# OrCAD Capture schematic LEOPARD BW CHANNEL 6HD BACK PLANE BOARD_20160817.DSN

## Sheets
1 001 COVER PAGE: title: 001 COVER PAGE; rev: SA; company: Wiwynn Corporation; note: LEOPARD BW CHANNEL BACK PLANE BOARD; note: 8F, No.90, Xintai 5th Rd., Xizhi Dist,; note: New Taipei, Taiwan
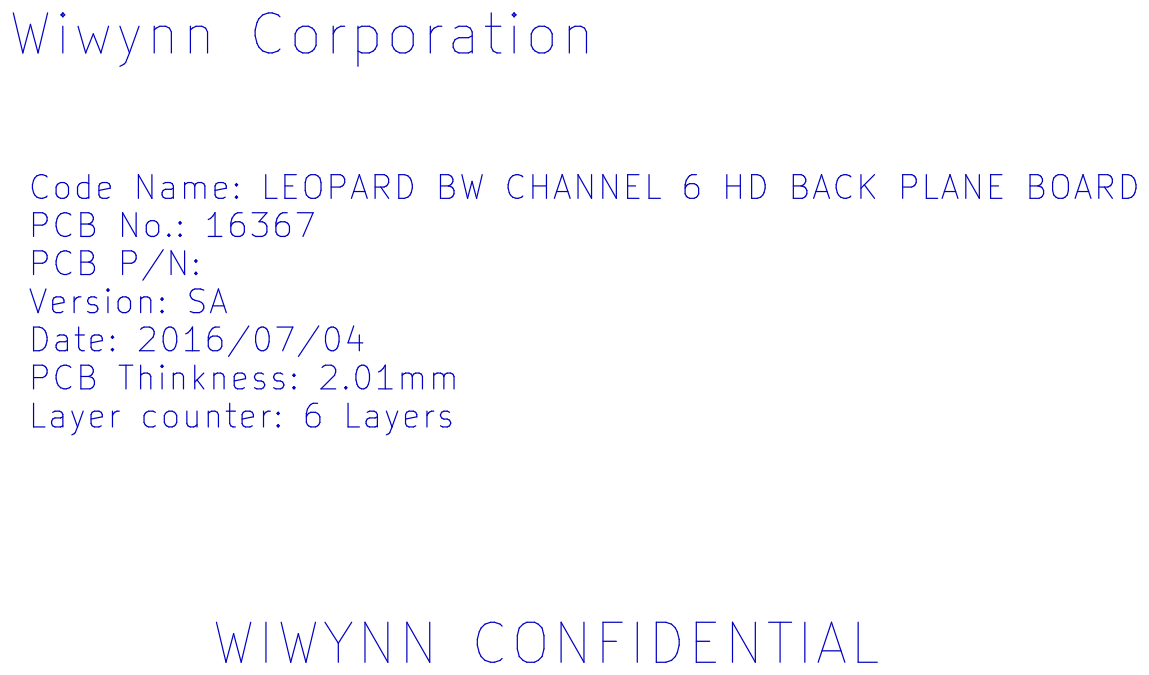
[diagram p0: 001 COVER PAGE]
2 007 SCREWS: size A4; title: 007 Screws; company: Wiwynn; note: 8F, 90, Sec.1, Hsin Tai Wu Rd.,; note: Hsichih, Taipei Hsien 221, Taiwan, R.O.C.
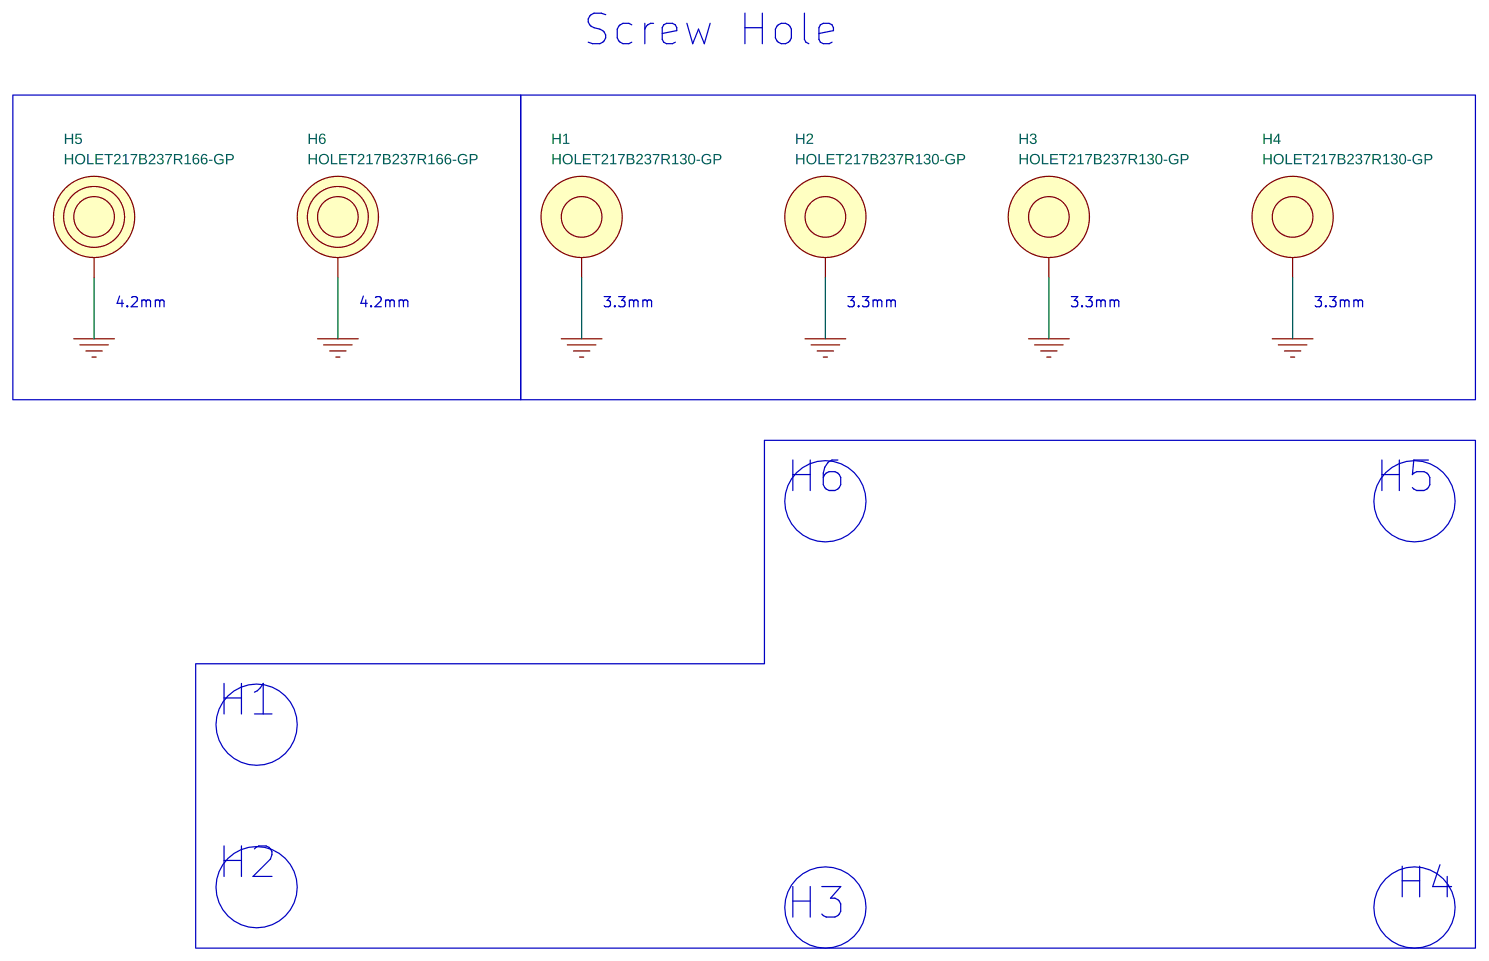
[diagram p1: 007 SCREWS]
3 006 MINISAS 1-2: size A3; title: 006 MiniSAS4i 1-2; company: Wiwynn; note: 8F, 90, Sec.1, Hsin Tai Wu Rd.,; note: Hsichih, Taipei Hsien 221, Taiwan, R.O.C.
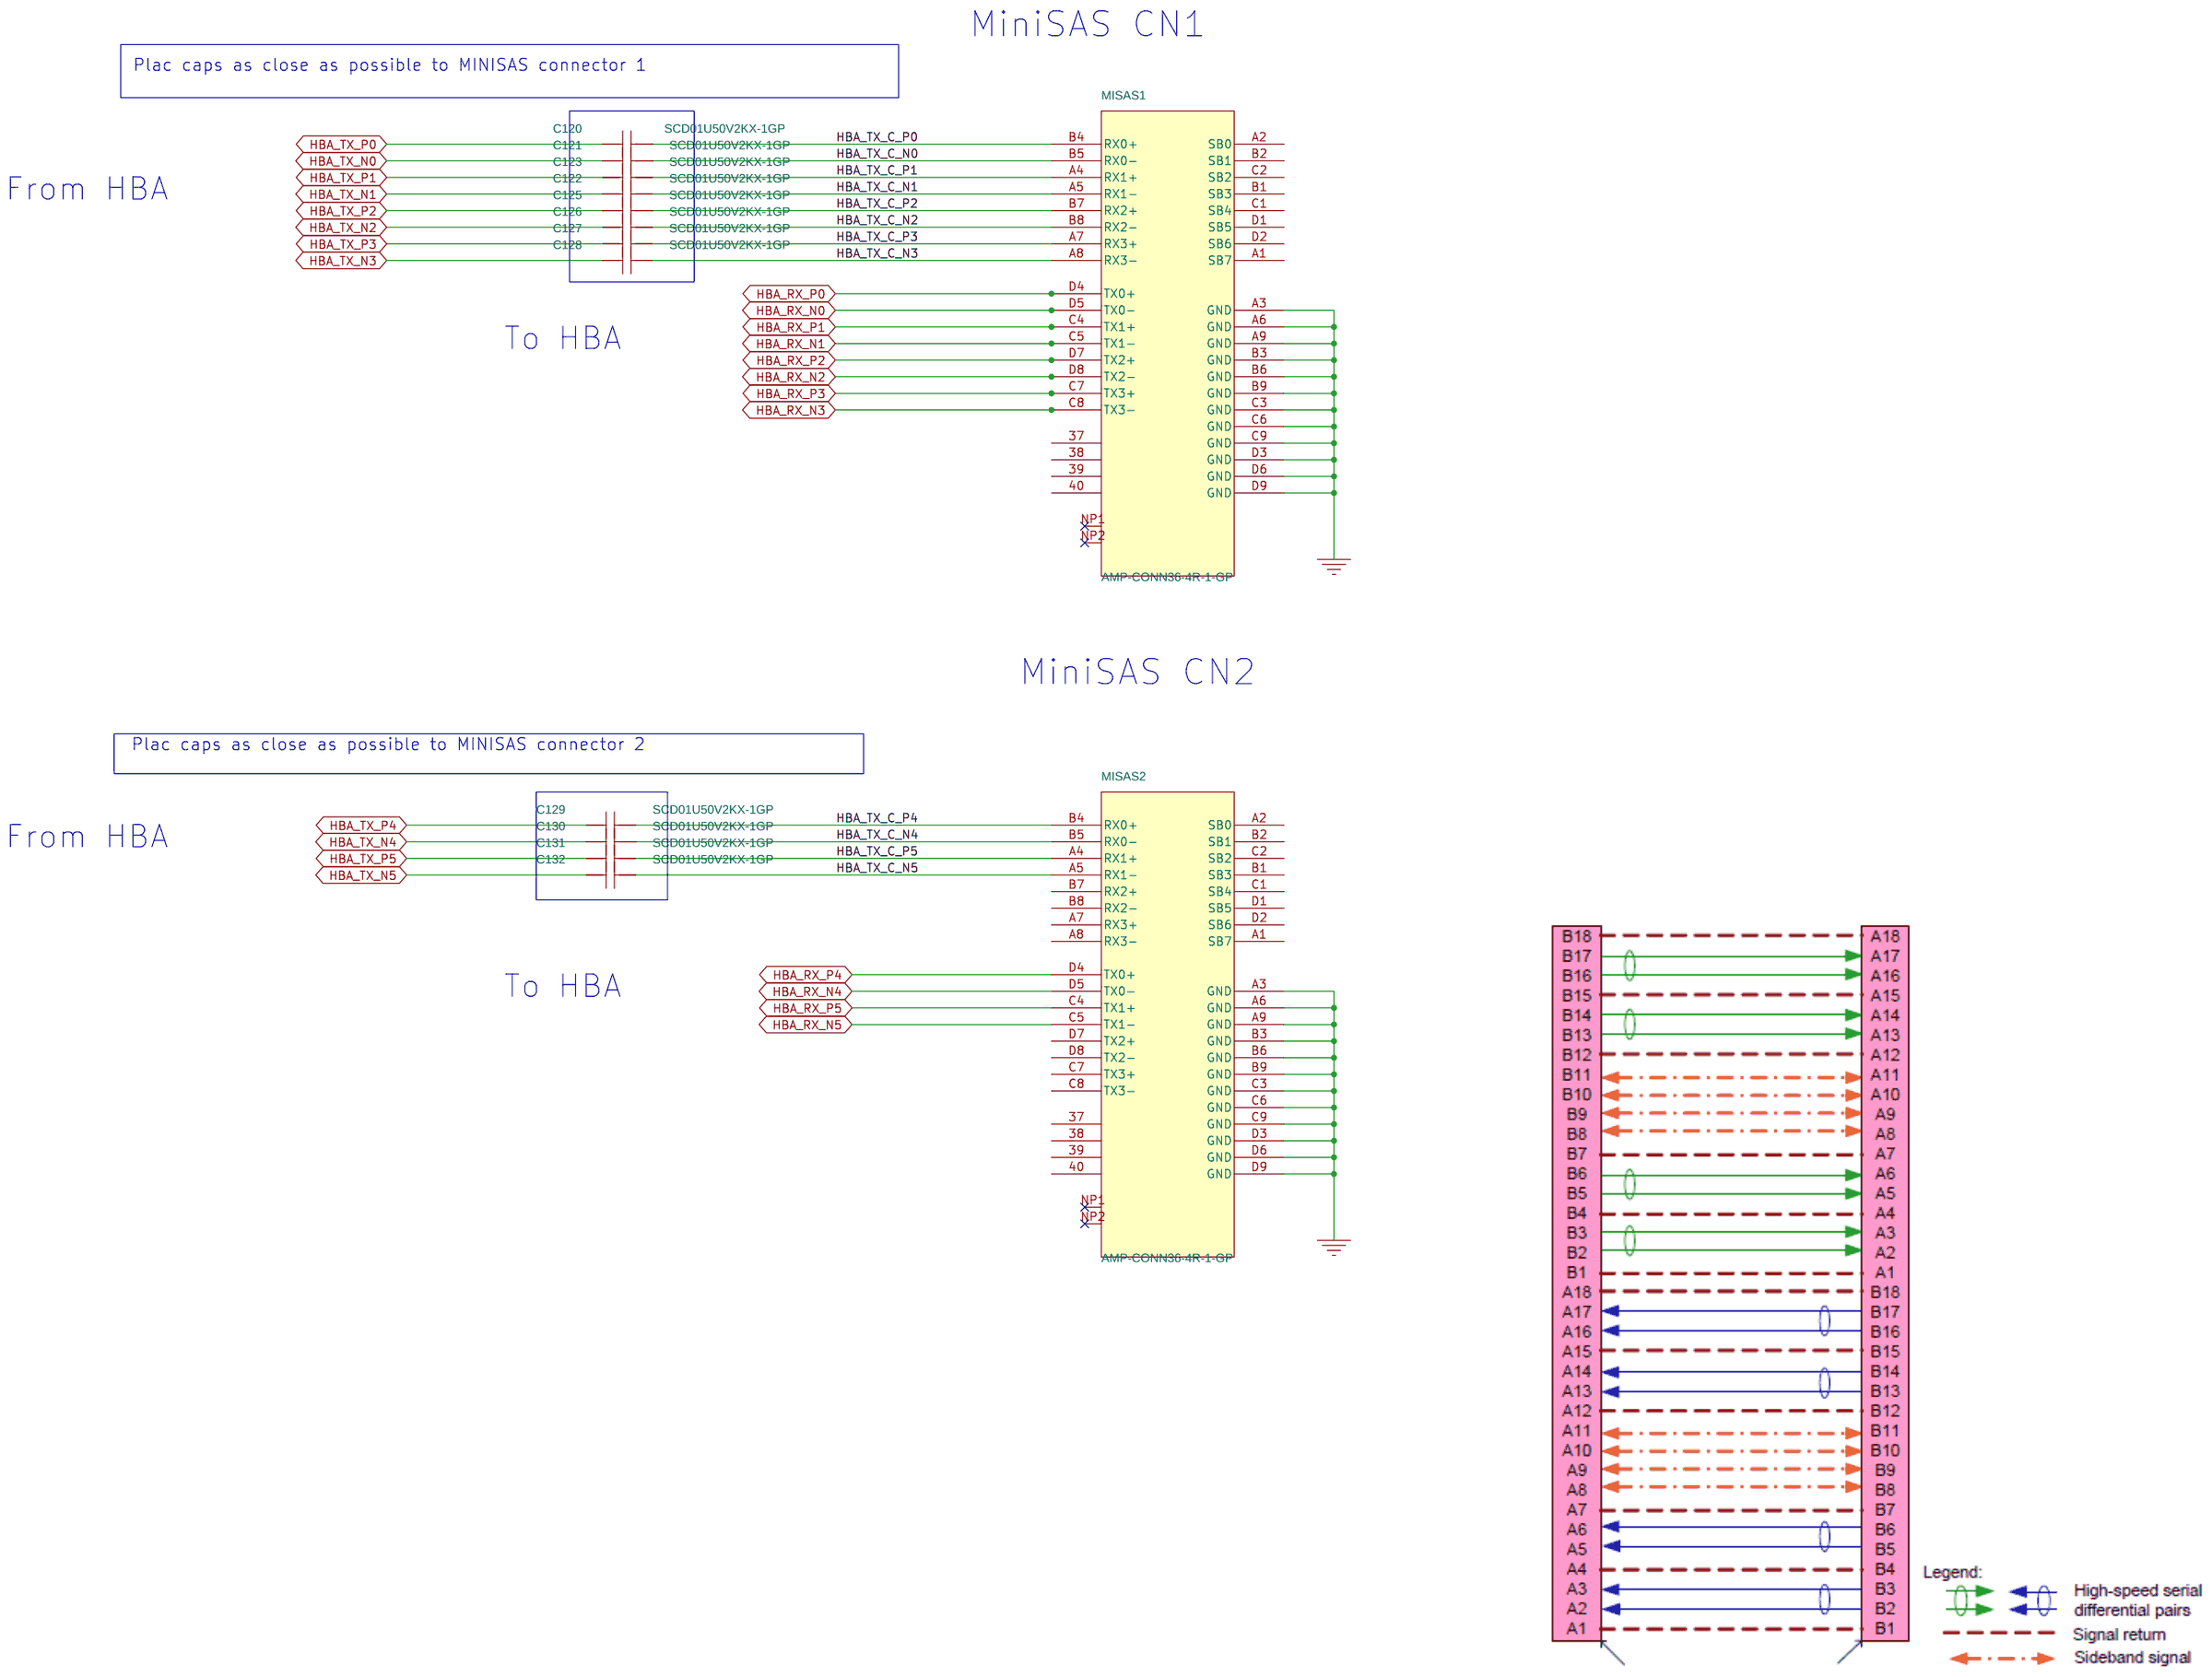
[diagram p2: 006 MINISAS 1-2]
4 005 POWER CONNECTOR: size A3; title: 005 PWR CN; company: Wiwynn; note: 8F, 90, Sec.1, Hsin Tai Wu Rd.,; note: Hsichih, Taipei Hsien 221, Taiwan, R.O.C.
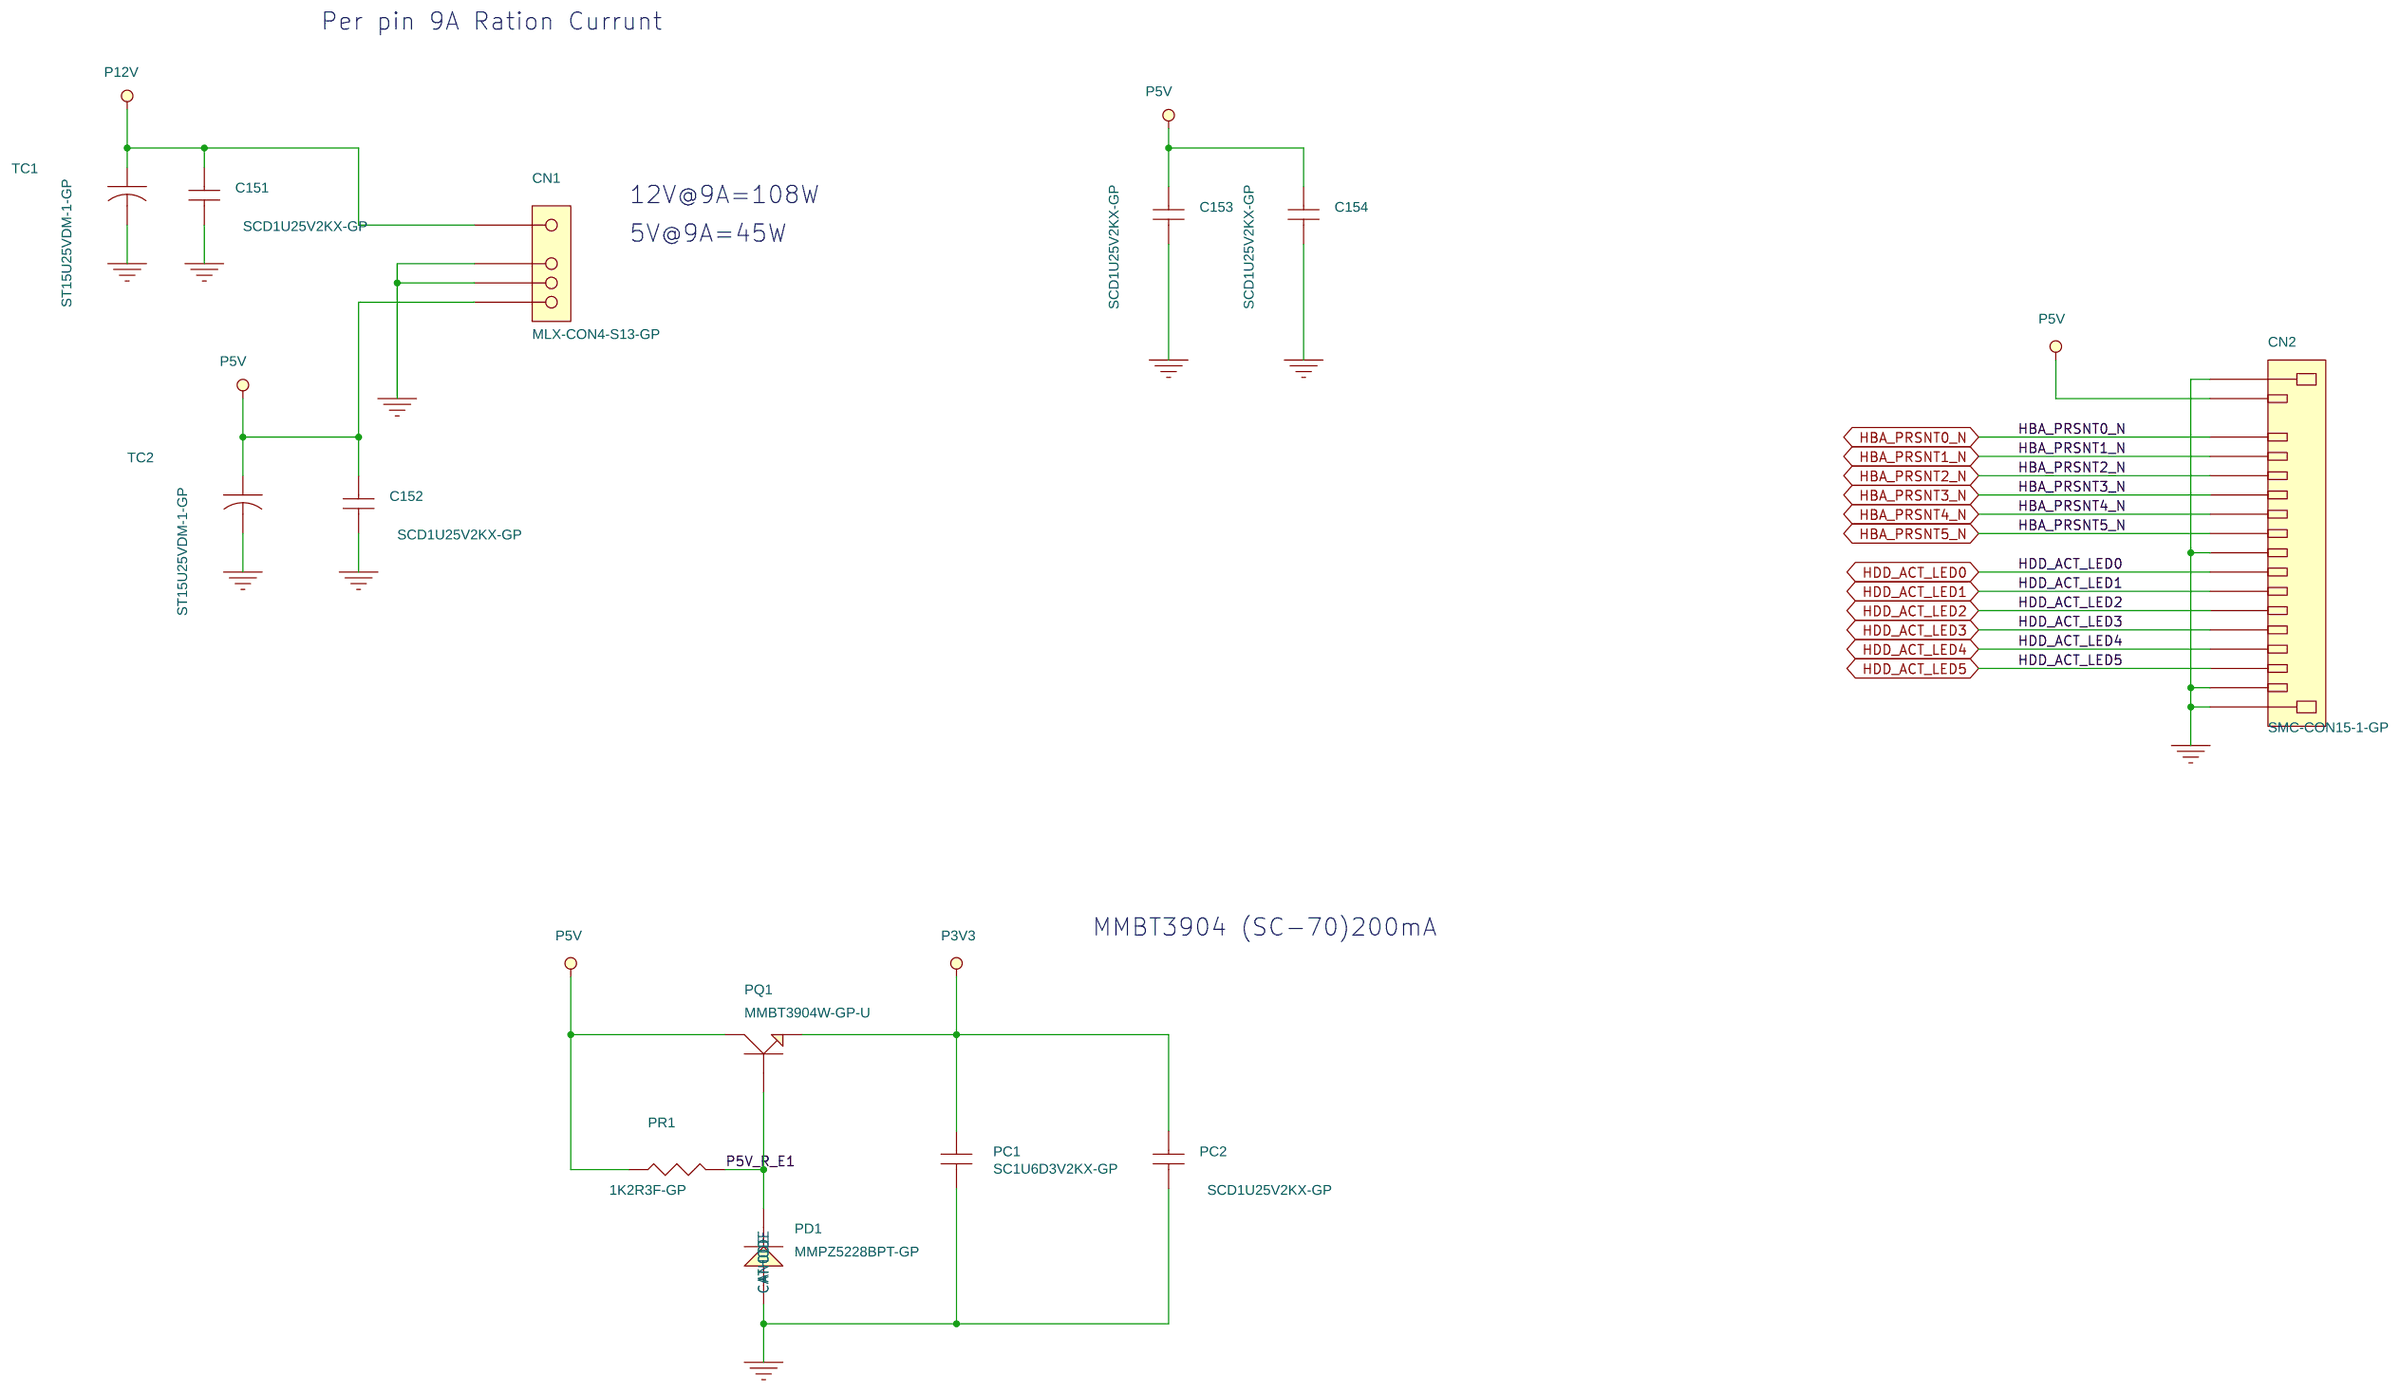
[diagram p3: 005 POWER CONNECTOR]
5 004 HDD SATA 5-6: size A2; title: 004 HDD SATA 5-6; company: Wiwynn; note: 8F, 90, Sec.1, Hsin Tai Wu Rd.,; note: Hsichih, Taipei Hsien 221, Taiwan, R.O.C.
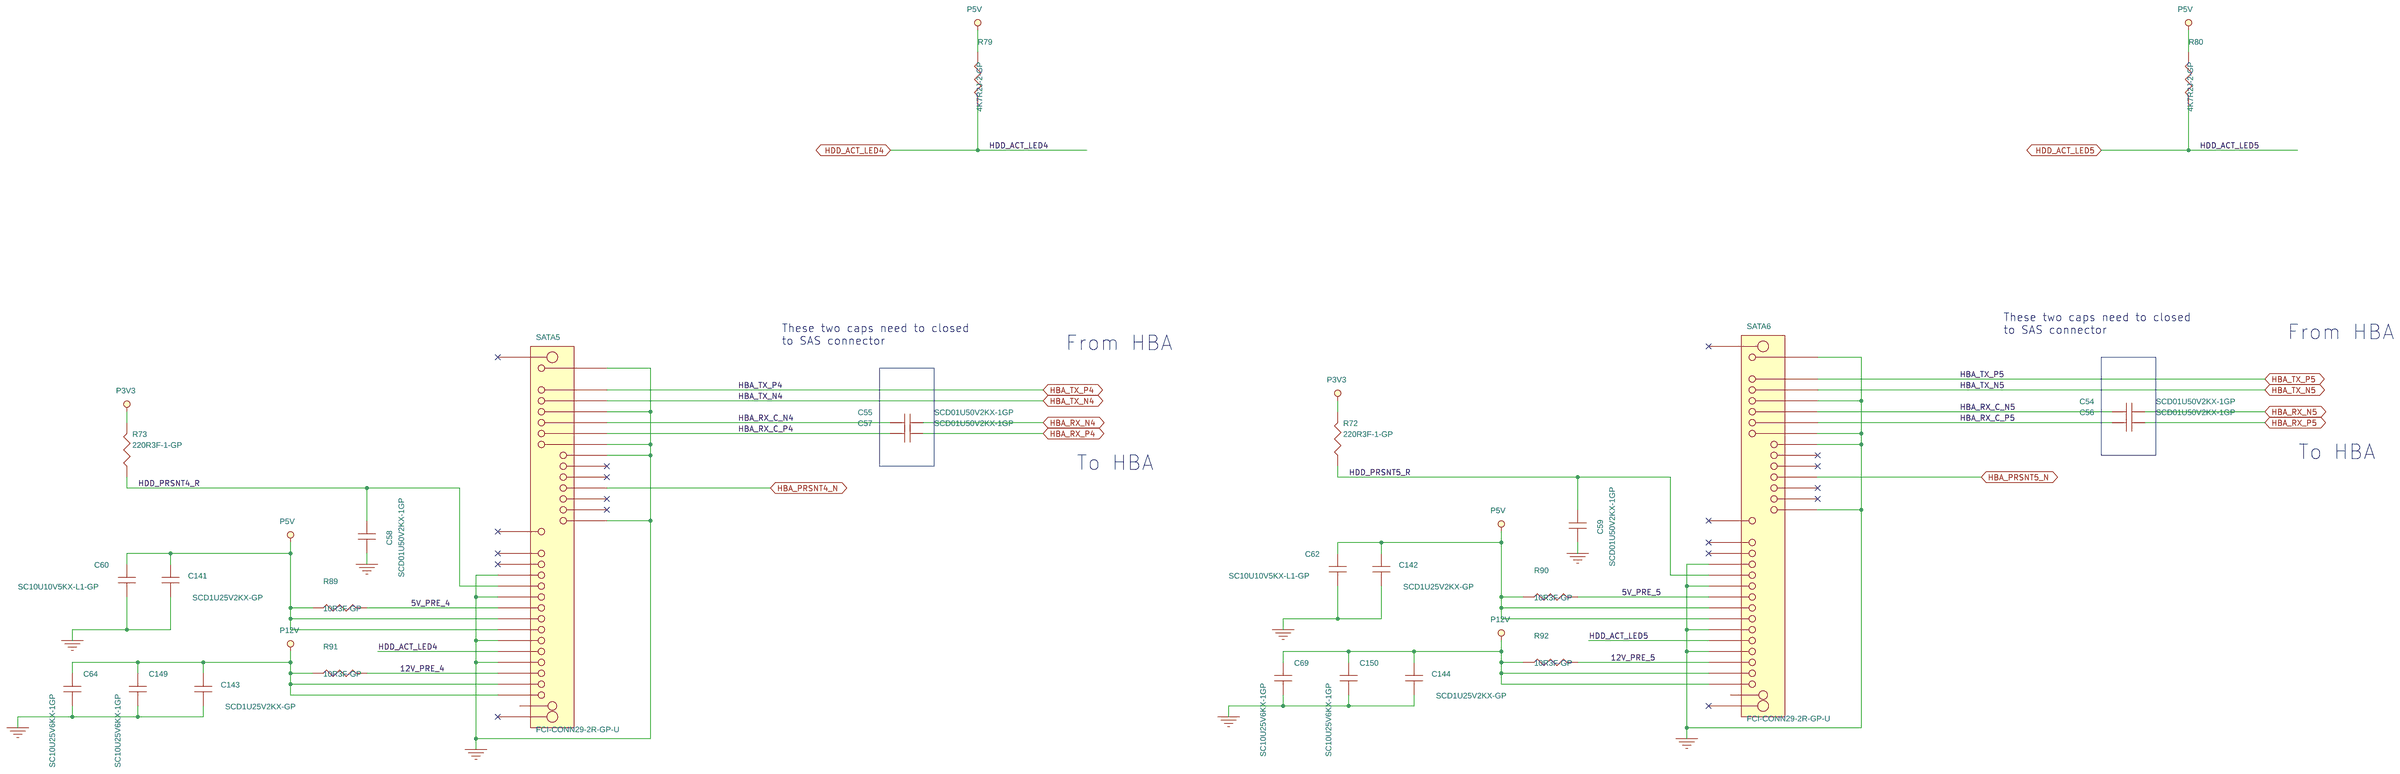
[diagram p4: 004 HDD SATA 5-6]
6 003 HDD SATA 1-4: size A2; title: 003 HDD SATA 1-4; company: Wiwynn; note: 8F, 90, Sec.1, Hsin Tai Wu Rd.,; note: Hsichih, Taipei Hsien 221, Taiwan, R.O.C.
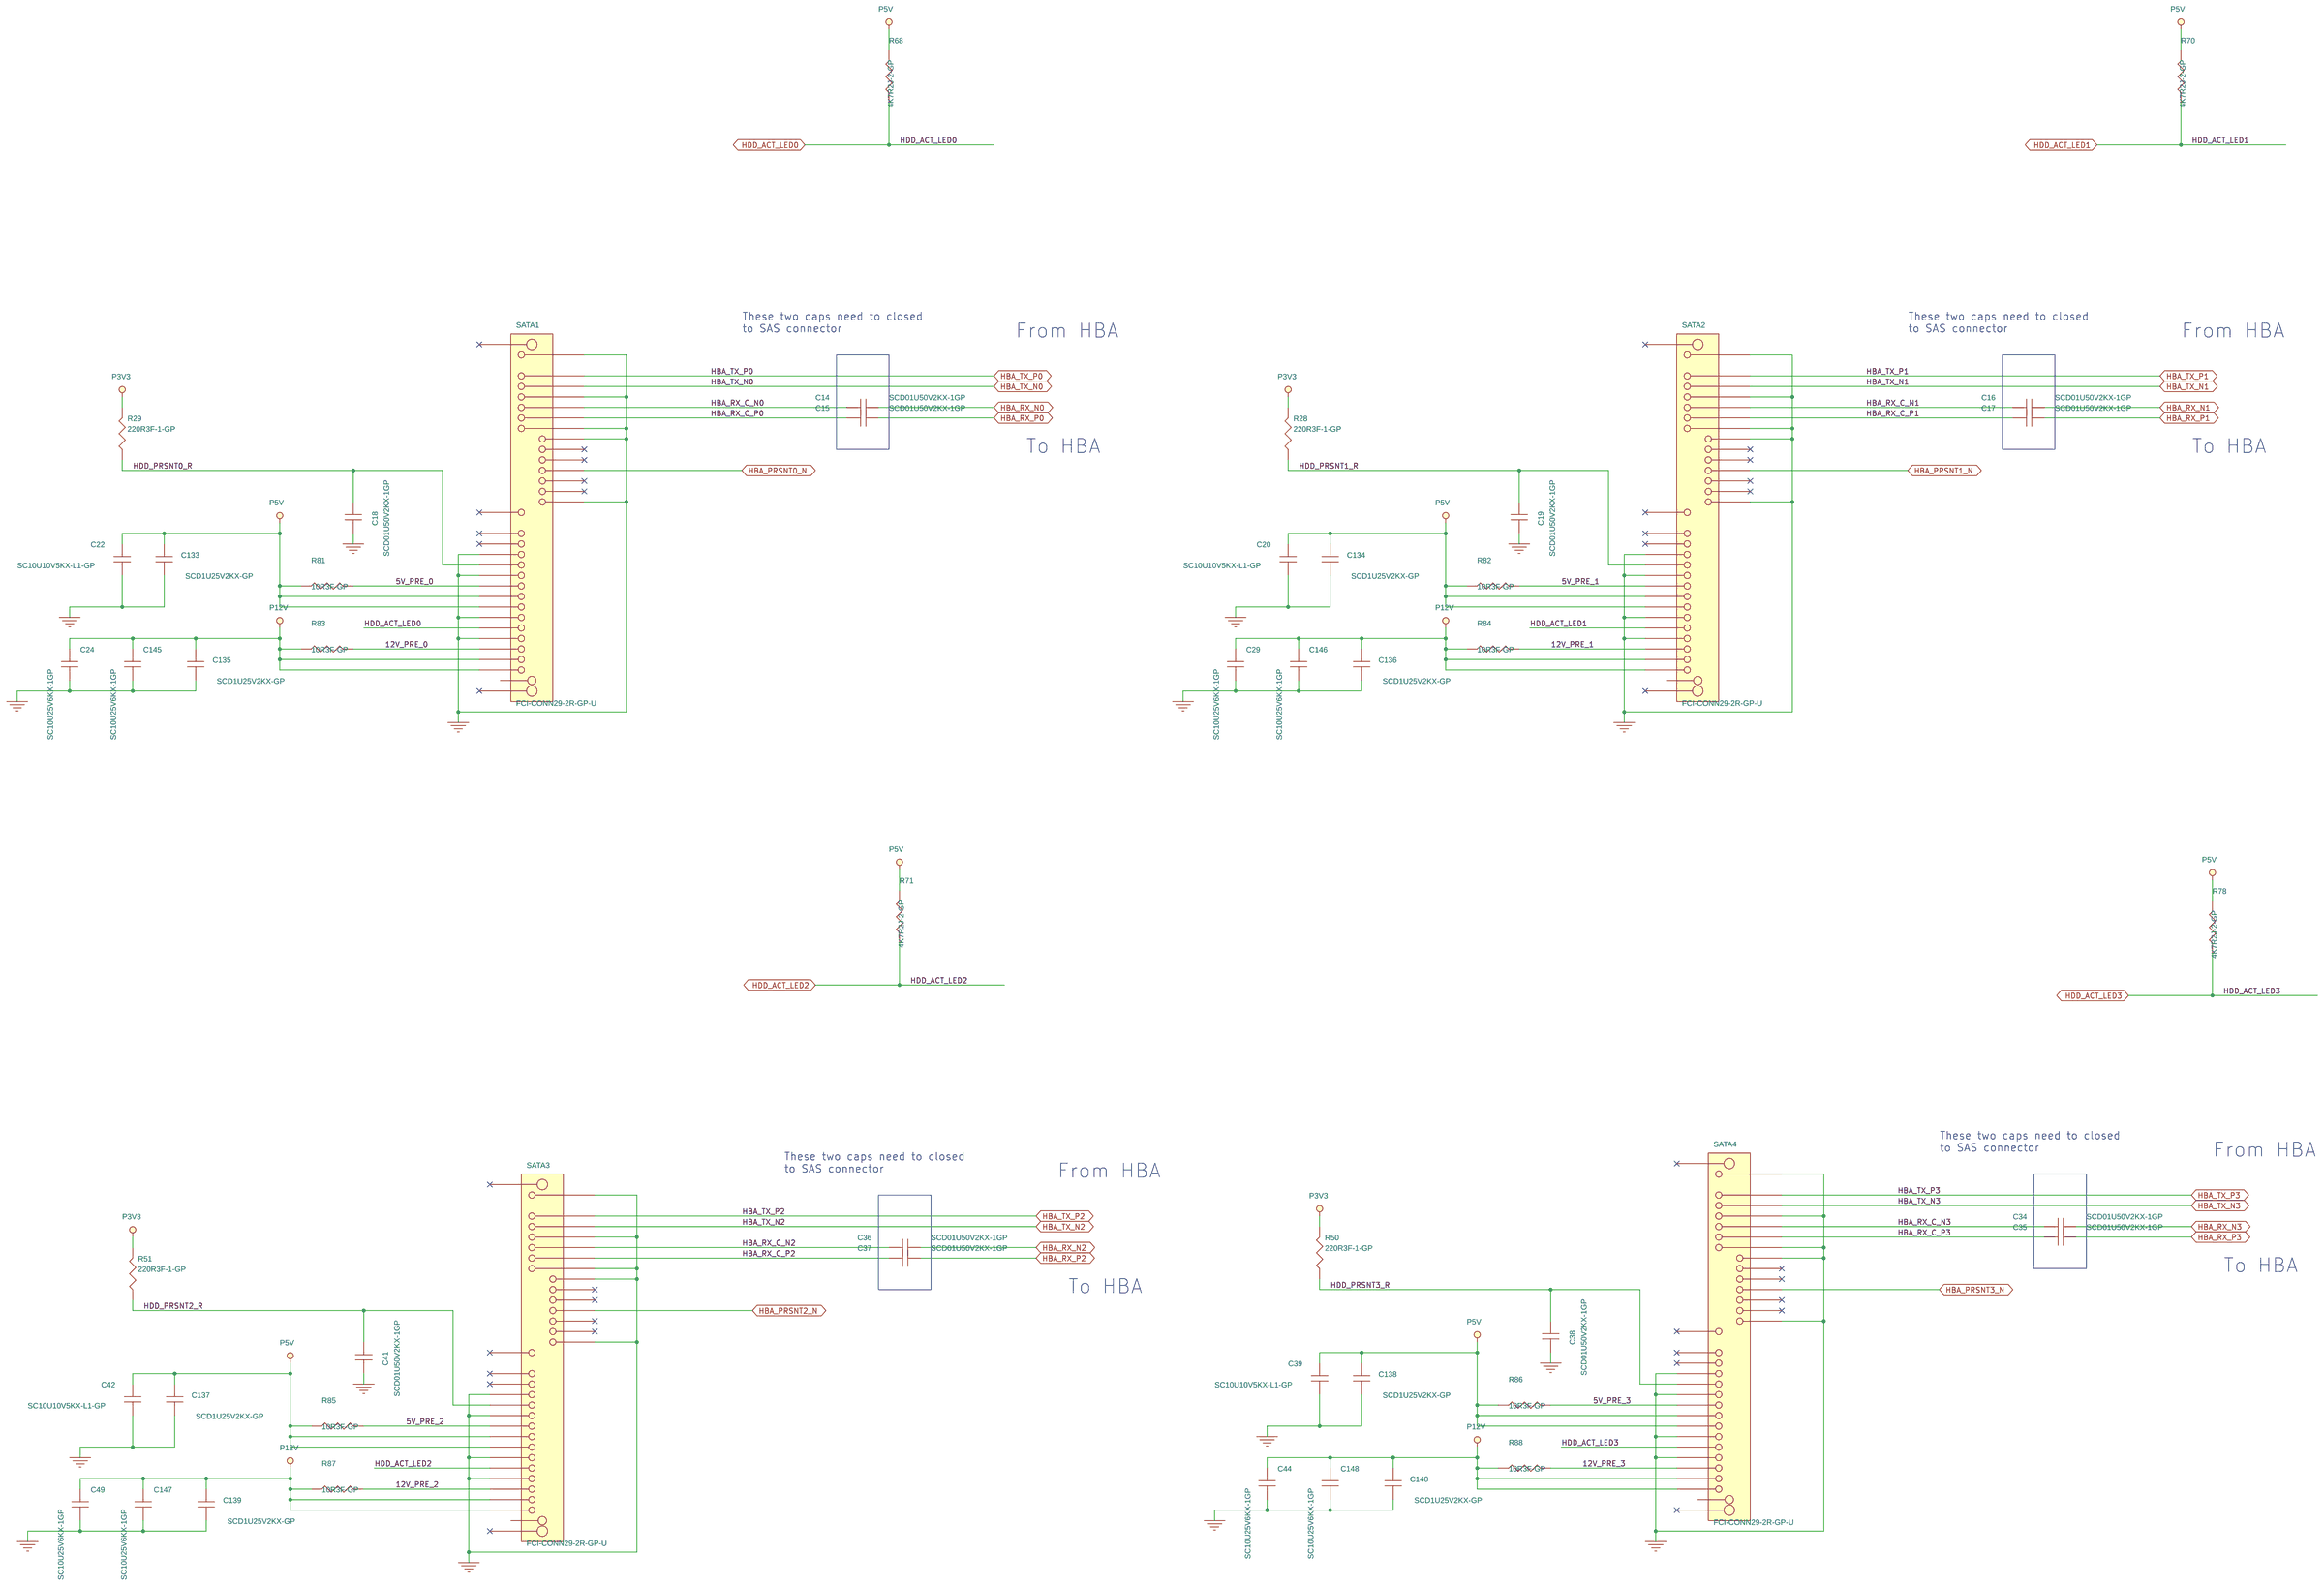
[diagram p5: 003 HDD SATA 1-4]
7 002 BLOCK DIAGRAM: title: 002 BLOCK DIAGRAM; company: Wiwynn; note: 8F, 90, Sec.1, Hsin Tai Wu Rd.,; note: Hsichih, Taipei Hsien 221, Taiwan, R.O.C.

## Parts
sheet 003 HDD SATA 1-4
C14  SCD01U50V2KX-1GP  [C402H22]
C15  SCD01U50V2KX-1GP  [C402H22]
C16  SCD01U50V2KX-1GP  [C402H22]
C17  SCD01U50V2KX-1GP  [C402H22]
C18  SCD01U50V2KX-1GP  [C402H22]
C19  SCD01U50V2KX-1GP  [C402H22]
C20  SC10U10V5KX-L1-GP  [C805H58]
C22  SC10U10V5KX-L1-GP  [C805H58]
C24  SC10U25V6KX-1GP  [C1206H71]
C29  SC10U25V6KX-1GP  [C1206H71]
C34  SCD01U50V2KX-1GP  [C402H22]
C35  SCD01U50V2KX-1GP  [C402H22]
C36  SCD01U50V2KX-1GP  [C402H22]
C37  SCD01U50V2KX-1GP  [C402H22]
C38  SCD01U50V2KX-1GP  [C402H22]
C39  SC10U10V5KX-L1-GP  [C805H58]
C41  SCD01U50V2KX-1GP  [C402H22]
C42  SC10U10V5KX-L1-GP  [C805H58]
C44  SC10U25V6KX-1GP  [C1206H71]
C49  SC10U25V6KX-1GP  [C1206H71]
C133  SCD1U25V2KX-GP  [C402H22]
C134  SCD1U25V2KX-GP  [C402H22]
C135  SCD1U25V2KX-GP  [C402H22]
C136  SCD1U25V2KX-GP  [C402H22]
C137  SCD1U25V2KX-GP  [C402H22]
C138  SCD1U25V2KX-GP  [C402H22]
C139  SCD1U25V2KX-GP  [C402H22]
C140  SCD1U25V2KX-GP  [C402H22]
C145  SC10U25V6KX-1GP  [C1206H71]
C146  SC10U25V6KX-1GP  [C1206H71]
C147  SC10U25V6KX-1GP  [C1206H71]
C148  SC10U25V6KX-1GP  [C1206H71]
R28  220R3F-1-GP  [R603H22]
R29  220R3F-1-GP  [R603H22]
R50  220R3F-1-GP  [R603H22]
R51  220R3F-1-GP  [R603H22]
R68  4K7R2J-2-GP  [R402H16]
R70  4K7R2J-2-GP  [R402H16]
R71  4K7R2J-2-GP  [R402H16]
R78  4K7R2J-2-GP  [R402H16]
R81  10R3F-GP  [R603H22]
R82  10R3F-GP  [R603H22]
R83  10R3F-GP  [R603H22]
R84  10R3F-GP  [R603H22]
R85  10R3F-GP  [R603H22]
R86  10R3F-GP  [R603H22]
R87  10R3F-GP  [R603H22]
R88  10R3F-GP  [R603H22]
SATA1  FCI-CONN29-2R-GP-U  [PREFIT-29P-458055-UH395]
SATA2  FCI-CONN29-2R-GP-U  [PREFIT-29P-458055-UH395]
SATA3  FCI-CONN29-2R-GP-U  [PREFIT-29P-458055-UH395]
SATA4  FCI-CONN29-2R-GP-U  [PREFIT-29P-458055-UH395]
sheet 004 HDD SATA 5-6
C54  SCD01U50V2KX-1GP  [C402H22]
C55  SCD01U50V2KX-1GP  [C402H22]
C56  SCD01U50V2KX-1GP  [C402H22]
C57  SCD01U50V2KX-1GP  [C402H22]
C58  SCD01U50V2KX-1GP  [C402H22]
C59  SCD01U50V2KX-1GP  [C402H22]
C60  SC10U10V5KX-L1-GP  [C805H58]
C62  SC10U10V5KX-L1-GP  [C805H58]
C64  SC10U25V6KX-1GP  [C1206H71]
C69  SC10U25V6KX-1GP  [C1206H71]
C141  SCD1U25V2KX-GP  [C402H22]
C142  SCD1U25V2KX-GP  [C402H22]
C143  SCD1U25V2KX-GP  [C402H22]
C144  SCD1U25V2KX-GP  [C402H22]
C149  SC10U25V6KX-1GP  [C1206H71]
C150  SC10U25V6KX-1GP  [C1206H71]
R72  220R3F-1-GP  [R603H22]
R73  220R3F-1-GP  [R603H22]
R79  4K7R2J-2-GP  [R402H16]
R80  4K7R2J-2-GP  [R402H16]
R89  10R3F-GP  [R603H22]
R90  10R3F-GP  [R603H22]
R91  10R3F-GP  [R603H22]
R92  10R3F-GP  [R603H22]
SATA5  FCI-CONN29-2R-GP-U  [PREFIT-29P-458055-UH395]
SATA6  FCI-CONN29-2R-GP-U  [PREFIT-29P-458055-UH395]
sheet 005 POWER CONNECTOR
C151  SCD1U25V2KX-GP  [C402H22]
C152  SCD1U25V2KX-GP  [C402H22]
C153  SCD1U25V2KX-GP  [C402H22]
C154  SCD1U25V2KX-GP  [C402H22]
CN1  MLX-CON4-S13-GP  [15-24-4449]
CN2  SMC-CON15-1-GP  [T1M-15-F-SV-L-P]
PC1  SC1U6D3V2KX-GP  [C402H22]
PC2  SCD1U25V2KX-GP  [C402H22]
PD1  MMPZ5228BPT-GP  [SOD323AKH40]
PQ1  MMBT3904W-GP-U  [SOT323CBE2D2H44]
PR1  1K2R3F-GP  [R603H22]
TC1  ST15U25VDM-1-GP  [CT7343H79]
TC2  ST15U25VDM-1-GP  [CT7343H79]
sheet 006 MINISAS 1-2
C120  SCD01U50V2KX-1GP  [C402H22]
C121  SCD01U50V2KX-1GP  [C402H22]
C122  SCD01U50V2KX-1GP  [C402H22]
C123  SCD01U50V2KX-1GP  [C402H22]
C125  SCD01U50V2KX-1GP  [C402H22]
C126  SCD01U50V2KX-1GP  [C402H22]
C127  SCD01U50V2KX-1GP  [C402H22]
C128  SCD01U50V2KX-1GP  [C402H22]
C129  SCD01U50V2KX-1GP  [C402H22]
C130  SCD01U50V2KX-1GP  [C402H22]
C131  SCD01U50V2KX-1GP  [C402H22]
C132  SCD01U50V2KX-1GP  [C402H22]
MISAS1  AMP-CONN36-4R-1-GP  [G40H2132212HR-W]
MISAS2  AMP-CONN36-4R-1-GP  [G40H2132212HR-W]
sheet 007 SCREWS
H1  HOLET217B237R130-GP  [HOLET217B237R130]
H2  HOLET217B237R130-GP  [HOLET217B237R130]
H3  HOLET217B237R130-GP  [HOLET217B237R130]
H4  HOLET217B237R130-GP  [HOLET217B237R130]
H5  HOLET217B237R166-GP  [HOLET217B237R166]
H6  HOLET217B237R166-GP  [HOLET217B237R166]

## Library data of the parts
C14-C19 C34-C38 C41 C54-C59 C120-C123 C125-C132 = SCD01U50V2KX-1GP: CHIP CAP C 0.01U 50V K0402 X7R; CATEGORIES: CAP_DCBATOUT; GREENDFACTOR: R2_SA;HF_SA;G_SA;; MAIN_SOURCE: M; POP?: POP; Part Number: 78.10324.2FL; Part Type: SMD-BCG; SPEC: http://wpqssvr.wistron.com.tw:7001/wpqs/servlet/COM.qpart.Attachment?PartNumber=78.10324.2FL
C20 C22 C39 C42 C60 C62 = SC10U10V5KX-L1-GP: CHIP CAP 10U 10V K0805 X5R 13" REEL; GREENDFACTOR: R2_SA;HF_SA;G_SA;; POP?: POP; Part Number: 78.10623.L1L; Part Type: SMD-BCG6; SPEC: http://wpqssvr.wistron.com.tw:7001/wpqs/servlet/COM.qpart.Attachment?PartNumber=78.10623.L1L
C24 C29 C44 C49 C64 C69 C145-C150 = SC10U25V6KX-1GP: CHIP CAP C 10U 25V K1206 X5R(R; CATEGORIES: CAP_1.xV; GREENDFACTOR: R2_SA;HF_SA;G_SA;; MAIN_SOURCE: M; POP?: POP; Package Type: SMD-BCG; Part Number: 78.10622.52L; Part Type: SMD-BCG; SPEC: http://wpqssvr.wistron.com.tw:7001/wpqs/servlet/COM.qpart.Attachment?PartNumber=78.10622.52L
C133-C144 C151-C154 PC2 = SCD1U25V2KX-GP: CHIP CAP C 0.1U 25V K0402 X5R; CATEGORIES: CAP_1.xV; Category: SATA; GREENDFACTOR: R2_SA;HF_SA;G_SA;; MAIN_SOURCE: M; POP?: POP; Part Number: 78.10422.5FL; Part Type: SMD-BCG1; SPEC: http://wpqssvr.wistron.com.tw:7001/wpqs/servlet/COM.qpart.Attachment?PartNumber=78.10422.5FL
R28 R29 R50 R51 R72 R73 = 220R3F-1-GP: CHIP RES 220 F 1/10W 0603; GREENDFACTOR: R2_SA;HF_SA;G_SA;; ORCAD_LIB: SMD-RG; POP?: POP; Part Number: 64.22005.55L; Part Type: SMD-RG; SPEC: http://wpqssvr.wistron.com.tw:7001/wpqs/servlet/COM.qpart.Attachment?PartNumber=64.22005.55L
R68 R70 R71 R78-R80 = 4K7R2J-2-GP: CHIP RES 4.7K J 1/16W 0402; GREENDFACTOR: R2_SA;HF_SA;G_SA;; POP?: POP; Part Number: 63.47234.1DL; Part Type: SMD-RG; SPEC: http://wpqssvr.wistron.com.tw:7001/wpqs/servlet/COM.qpart.Attachment?PartNumber=63.47234.1DL
R81-R92 = 10R3F-GP: CHIP RES 10 F 1/10W 0603; Category: VR_P1V8_PLL_CPU1; GREENDFACTOR: R2_SA;HF_SA;G_SA;; POP?: POP; Package Type: RCL_GP; Part Number: 64.10R05.55L; Part Type: RCL_GP; SPEC: http://wpqssvr.wistron.com.tw:7001/wpqs/servlet/COM.qpart.Attachment?PartNumber=64.10R05.55L
SATA1-SATA6 = FCI-CONN29-2R-GP-U: CONN CTR 2R29P 10031077-001LF; Part Number: 20.81491.029; Part Type: CONN-G2; SPEC: http://wpqssvr.wistron.com.tw:7001/wpqs/servlet/COM.qpart.Attachment?PartNumber=20.81491.029
CN1 = MLX-CON4-S13-GP: HEAD ML 1R4P ST 15-24-4449 ,LCP; GREENDFACTOR: R2_SA;; Part Number: 21.60929.104; Part Type: CONN-G7; SPEC: http://wpqssvr.wistron.com.tw:7001/wpqs/servlet/COM.qpart.Attachment?PartNumber=21.60929.104
CN2 = SMC-CON15-1-GP: HEAD ML 1R15P T1M-15-F-SV-L-P SMD; Part Number: 021.D0235.0115; Part Type: CONN-G3; SPEC: http://wpqssvr.wistron.com.tw:7001/wpqs/servlet/COM.qpart.Attachment?PartNumber=L%252BlhhJdIDDBEv8X7LMffxA%253D%253D
PC1 = SC1U6D3V2KX-GP: CHIP CAP C 1U 6.3V K0402 X5R; CATEGORIES: CAP_1.xV; GREENDFACTOR: R2_SA;HF_SA;G_SA;; MAIN_SOURCE: M; POP?: POP; Part Number: 78.10520.5FL; Part Type: SMD-BCG; SPEC: http://wpqssvr.wistron.com.tw:7001/wpqs/servlet/COM.qpart.Attachment?PartNumber=78.10520.5FL
PD1 = MMPZ5228BPT-GP: DIODE ZEN MMPZ5228BPT SOD-323; Category: VR_SYS; GREENDFACTOR: R_SA;; Level: SMT; POP?: POP; Part Number: 83.3R903.B3F; Part Type: DISCRET-G; SPEC: http://wpqssvr.wistron.com.tw:7001/wpqs/servlet/COM.qpart.Attachment?PartNumber=83.3R903.B3F; Status: NPOP
PQ1 = MMBT3904W-GP-U: XTOR MMBT3904W NPN SOT-323; GREENDFACTOR: R2_SA;HF_SA;; Part Number: 84.M3904.A11; Part Type: DISCRET-G5; SPEC: http://wpqssvr.wistron.com.tw:7001/wpqs/servlet/COM.qpart.Attachment?PartNumber=84.M3904.A11
PR1 = 1K2R3F-GP: CHIP RES 1.2K F 1/10W0603(ROHS; GREENDFACTOR: R2_SA;HF_SA;G_SA;; POP?: POP; Part Number: 64.12015.55L; Part Type: RCL_GP; SPEC: http://wpqssvr.wistron.com.tw:7001/wpqs/servlet/COM.qpart.Attachment?PartNumber=64.12015.55L
TC1 TC2 = ST15U25VDM-1-GP: CHIP CAP POS 15U 25V 25TQC15M; GREENDFACTOR: R2_SA;HF_SA;G_SA;; POP?: POP; Part Number: 77.21561.00L; Part Type: SMD-TCG; SPEC: http://wpqssvr.wistron.com.tw:7001/wpqs/servlet/COM.qpart.Attachment?PartNumber=77.21561.00L
MISAS1 MISAS2 = AMP-CONN36-4R-1-GP: CONN CTR 36P MINI SAS G40H2132212HR-W; GREENDFACTOR: R2_SA;; Part Number: 20.F2319.036; Part Type: CONN-G3; SPEC: http://wpqssvr.wistron.com.tw:7001/wpqs/servlet/COM.qpart.Attachment?PartNumber=20.F2319.036
H1-H4 = HOLET217B237R130-GP: SCREW HOLE 3.3MM FOR R1113IL1; GREENDFACTOR: R2_C;; Part Number: ZZ.SCREW.D31; Part Type: DISCRET-G9; SPEC: http://wpqssvr.wistron.com.tw:7001/wpqs/servlet/COM.qpart.Attachment?PartNumber=ZZ.SCREW.D31
H5 H6 = HOLET217B237R166-GP: SCREW HOLE 4.2MM FOR R1113IL1; GREENDFACTOR: R2_C;; Part Number: ZZ.SCREW.D41; Part Type: DISCRET-G9; SPEC: http://wpqssvr.wistron.com.tw:7001/wpqs/servlet/COM.qpart.Attachment?PartNumber=ZZ.SCREW.D41

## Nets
5V_PRE_0: R81.2 SATA1.P7
5V_PRE_1: R82.2 SATA2.P7
5V_PRE_2: R85.2 SATA3.P7
5V_PRE_3: R86.2 SATA4.P7
5V_PRE_4: R89.2 SATA5.P7
5V_PRE_5: R90.2 SATA6.P7
12V_PRE_0: R83.2 SATA1.P13
12V_PRE_1: R84.2 SATA2.P13
12V_PRE_2: R87.2 SATA3.P13
12V_PRE_3: R88.2 SATA4.P13
12V_PRE_4: R91.2 SATA5.P13
12V_PRE_5: R92.2 SATA6.P13
GND: C18.2 C19.2 C20.2 C22.2 C24.2 C29.2 C38.2 C39.2 C41.2 C42.2 C44.2 C49.2 C58.2 C59.2 C60.2 C62.2 C64.2 C69.2 C133.2 C134.2 C135.2 C136.2 C137.2 C138.2 C139.2 C140.2 C141.2 C142.2 C143.2 C144.2 C145.2 C146.2 C147.2 C148.2 C149.2 C150.2 C151.2 C152.2 C153.2 C154.2 CN1.2 CN1.3 CN2.8 CN2.15 CN2.PTH1 CN2.PTH2 H1.1 H2.1 H3.1 H4.1 H5.1 H6.1 MISAS1.A3(GND) MISAS1.A6(GND) MISAS1.A9(GND) MISAS1.B3(GND) MISAS1.B6(GND) MISAS1.B9(GND) MISAS1.C3(GND) MISAS1.C6(GND) MISAS1.C9(GND) MISAS1.D3(GND) MISAS1.D6(GND) MISAS1.D9(GND) MISAS2.A3(GND) MISAS2.A6(GND) MISAS2.A9(GND) MISAS2.B3(GND) MISAS2.B6(GND) MISAS2.B9(GND) MISAS2.C3(GND) MISAS2.C6(GND) MISAS2.C9(GND) MISAS2.D3(GND) MISAS2.D6(GND) MISAS2.D9(GND) PC1.2 PC2.2 PD1.A(ANODE) SATA1.P4 SATA1.P6 SATA1.P10 SATA1.P12 SATA1.S1 SATA1.S4 SATA1.S7 SATA1.S8 SATA1.S14 SATA2.P4 SATA2.P6 SATA2.P10 SATA2.P12 SATA2.S1 SATA2.S4 SATA2.S7 SATA2.S8 SATA2.S14 SATA3.P4 SATA3.P6 SATA3.P10 SATA3.P12 SATA3.S1 SATA3.S4 SATA3.S7 SATA3.S8 SATA3.S14 SATA4.P4 SATA4.P6 SATA4.P10 SATA4.P12 SATA4.S1 SATA4.S4 SATA4.S7 SATA4.S8 SATA4.S14 SATA5.P4 SATA5.P6 SATA5.P10 SATA5.P12 SATA5.S1 SATA5.S4 SATA5.S7 SATA5.S8 SATA5.S14 SATA6.P4 SATA6.P6 SATA6.P10 SATA6.P12 SATA6.S1 SATA6.S4 SATA6.S7 SATA6.S8 SATA6.S14 TC1.2 TC2.2
P3V3: PC1.1 PC2.1 PQ1.E R28.2 R29.2 R50.2 R51.2 R72.2 R73.2
P5V: C20.1 C22.1 C39.1 C42.1 C60.1 C62.1 C133.1 C134.1 C137.1 C138.1 C141.1 C142.1 C152.1 C153.1 C154.1 CN1.4 CN2.1 PQ1.C PR1.1 R68.2 R70.2 R71.2 R78.2 R79.2 R80.2 R81.1 R82.1 R85.1 R86.1 R89.1 R90.1 SATA1.P8 SATA1.P9 SATA2.P8 SATA2.P9 SATA3.P8 SATA3.P9 SATA4.P8 SATA4.P9 SATA5.P8 SATA5.P9 SATA6.P8 SATA6.P9 TC2.1
P5V_R_E1: PD1.K(CATHODE) PQ1.B PR1.2
P12V: C24.1 C29.1 C44.1 C49.1 C64.1 C69.1 C135.1 C136.1 C139.1 C140.1 C143.1 C144.1 C145.1 C146.1 C147.1 C148.1 C149.1 C150.1 C151.1 CN1.1 R83.1 R84.1 R87.1 R88.1 R91.1 R92.1 SATA1.P14 SATA1.P15 SATA2.P14 SATA2.P15 SATA3.P14 SATA3.P15 SATA4.P14 SATA4.P15 SATA5.P14 SATA5.P15 SATA6.P14 SATA6.P15 TC1.1
HBA_PRSNT0_N: CN2.2 SATA1.S11
HBA_PRSNT1_N: CN2.3 SATA2.S11
HBA_PRSNT2_N: CN2.4 SATA3.S11
HBA_PRSNT3_N: CN2.5 SATA4.S11
HBA_PRSNT4_N: CN2.6 SATA5.S11
HBA_PRSNT5_N: CN2.7 SATA6.S11
HBA_RX_C_N0: C14.2 SATA1.S5
HBA_RX_C_N1: C16.2 SATA2.S5
HBA_RX_C_N2: C36.2 SATA3.S5
HBA_RX_C_N3: C34.2 SATA4.S5
HBA_RX_C_N4: C55.2 SATA5.S5
HBA_RX_C_N5: C54.2 SATA6.S5
HBA_RX_C_P0: C15.2 SATA1.S6
HBA_RX_C_P1: C17.2 SATA2.S6
HBA_RX_C_P2: C37.2 SATA3.S6
HBA_RX_C_P3: C35.2 SATA4.S6
HBA_RX_C_P4: C57.2 SATA5.S6
HBA_RX_C_P5: C56.2 SATA6.S6
HBA_RX_N0: C14.1 MISAS1.D5(TX0-)
HBA_RX_N1: C16.1 MISAS1.C5(TX1-)
HBA_RX_N2: C36.1 MISAS1.D8(TX2-)
HBA_RX_N3: C34.1 MISAS1.C8(TX3-)
HBA_RX_N4: C55.1 MISAS2.D5(TX0-)
HBA_RX_N5: C54.1 MISAS2.C5(TX1-)
HBA_RX_P0: C15.1 MISAS1.D4(TX0+)
HBA_RX_P1: C17.1 MISAS1.C4(TX1+)
HBA_RX_P2: C37.1 MISAS1.D7(TX2+)
HBA_RX_P3: C35.1 MISAS1.C7(TX3+)
HBA_RX_P4: C57.1 MISAS2.D4(TX0+)
HBA_RX_P5: C56.1 MISAS2.C4(TX1+)
HBA_TX_C_N0: C121.2 MISAS1.B5(RX0-)
HBA_TX_C_N1: C122.2 MISAS1.A5(RX1-)
HBA_TX_C_N2: C126.2 MISAS1.B8(RX2-)
HBA_TX_C_N3: C128.2 MISAS1.A8(RX3-)
HBA_TX_C_N4: C130.2 MISAS2.B5(RX0-)
HBA_TX_C_N5: C132.2 MISAS2.A5(RX1-)
HBA_TX_C_P0: C120.2 MISAS1.B4(RX0+)
HBA_TX_C_P1: C123.2 MISAS1.A4(RX1+)
HBA_TX_C_P2: C125.2 MISAS1.B7(RX2+)
HBA_TX_C_P3: C127.2 MISAS1.A7(RX3+)
HBA_TX_C_P4: C129.2 MISAS2.B4(RX0+)
HBA_TX_C_P5: C131.2 MISAS2.A4(RX1+)
HBA_TX_N0: C121.1 SATA1.S3
HBA_TX_N1: C122.1 SATA2.S3
HBA_TX_N2: C126.1 SATA3.S3
HBA_TX_N3: C128.1 SATA4.S3
HBA_TX_N4: C130.1 SATA5.S3
HBA_TX_N5: C132.1 SATA6.S3
HBA_TX_P0: C120.1 SATA1.S2
HBA_TX_P1: C123.1 SATA2.S2
HBA_TX_P2: C125.1 SATA3.S2
HBA_TX_P3: C127.1 SATA4.S2
HBA_TX_P4: C129.1 SATA5.S2
HBA_TX_P5: C131.1 SATA6.S2
HDD_ACT_LED0: CN2.9 R68.1 SATA1.P11
HDD_ACT_LED1: CN2.10 R70.1 SATA2.P11
HDD_ACT_LED2: CN2.11 R71.1 SATA3.P11
HDD_ACT_LED3: CN2.12 R78.1 SATA4.P11
HDD_ACT_LED4: CN2.13 R79.1 SATA5.P11
HDD_ACT_LED5: CN2.14 R80.1 SATA6.P11
HDD_PRSNT0_R: C18.1 R29.1 SATA1.P5
HDD_PRSNT1_R: C19.1 R28.1 SATA2.P5
HDD_PRSNT2_R: C41.1 R51.1 SATA3.P5
HDD_PRSNT3_R: C38.1 R50.1 SATA4.P5
HDD_PRSNT4_R: C58.1 R73.1 SATA5.P5
HDD_PRSNT5_R: C59.1 R72.1 SATA6.P5

Not connected (* = marked no-connect by the designer): MISAS1 37 38 39 40 A1(SB7) A2(SB0) B1(SB3) B2(SB1) C1(SB4) C2(SB2) D1(SB5) D2(SB6) NP1* NP2*; MISAS2 37 38 39 40 A1(SB7) A2(SB0) A7(RX3+) A8(RX3-) B1(SB3) B2(SB1) B7(RX2+) B8(RX2-) C1(SB4) C2(SB2) C7(TX3+) C8(TX3-) D1(SB5) D2(SB6) D7(TX2+) D8(TX2-) NP1* NP2*; SATA1 30* 31* NP1 P1* P2* P3* S9* S10* S12* S13*; SATA2 30* 31* NP1 P1* P2* P3* S9* S10* S12* S13*; SATA3 30* 31* NP1 P1* P2* P3* S9* S10* S12* S13*; SATA4 30* 31* NP1 P1* P2* P3* S9* S10* S12* S13*; SATA5 30* 31* NP1 P1* P2* P3* S9* S10* S12* S13*; SATA6 30* 31* NP1 P1* P2* P3* S9* S10* S12* S13*

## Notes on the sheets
sheet 1
- Wiwynn Corporation
- Code Name: LEOPARD BW CHANNEL 6 HD BACK PLANE BOARD
  PCB No.: 16367
  PCB P/N:
  Version: SA
  Date: 2016/07/04
  PCB Thinkness: 2.01mm
  Layer counter: 6 Layers
- WIWYNN CONFIDENTIAL
sheet 2
- Screw Hole
- 4.2mm
- 4.2mm
- 3.3mm
- 3.3mm
- 3.3mm
- 3.3mm
- H6
- H5
- H1
- H2
- H3
- H4
sheet 3
- MiniSAS CN1
- Plac caps as close as possible to MINISAS connector 1
- From HBA
- To HBA
- MiniSAS CN2
- Plac caps as close as possible to MINISAS connector 2
- From HBA
- To HBA
sheet 4
- Per pin 9A Ration Currunt
- 12V@9A=108W
- 5V@9A=45W
- MMBT3904 (SC-70)200mA
sheet 5
- These two caps need to closed
  to SAS connector
- These two caps need to closed
  to SAS connector
- From HBA
- From HBA
- To HBA
- To HBA
sheet 6
- These two caps need to closed
  to SAS connector
- These two caps need to closed
  to SAS connector
- From HBA
- From HBA
- To HBA
- To HBA
- These two caps need to closed
  to SAS connector
- From HBA
- These two caps need to closed
  to SAS connector
- From HBA
- To HBA
- To HBA
